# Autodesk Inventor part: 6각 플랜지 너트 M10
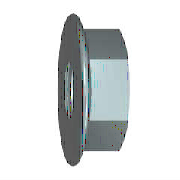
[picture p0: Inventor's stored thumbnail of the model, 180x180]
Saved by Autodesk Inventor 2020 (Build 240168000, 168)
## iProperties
Created: 2012-02
Part Number: 6각 플랜지 너트 M10
Material: 강철, 연강
Description: 플랜지붙이 6각 너트
Document SubType Name: Modeling
Standard: JIS B 1190
Designer: mdu-01
Standards Organization: JIS
Language: ko-KR
Size Designation: M 10
Categories: <MemberInstance><Categories><Category DisplayName="조임쇠" InternalName="e4da775c-781d-43d5-af7c-5136215cf5a6" Mnemonic="FSTN"><Category DisplayName="너트" InternalN
Density: 1 g/cm^3
Appearance: Steel
IsCustomPart: 1
Author: mdu-01
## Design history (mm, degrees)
sketch "스케치1"
  geometry: L1 (-2.276, 0)-(12.046, 0) reference; L2 (3.914, 7)-(2.239, 9.9); L3 (3.914, 7)-(10, 7); L4 (10, 7)-(10, 0); L5 (3.914, 7)-(3.914, 0); L6 (0, -2.152)-(0, 12.911) reference; A1 r 1.2 centre (1.2, 9.3) between (2.239, 9.9) and (0, 9.3); 1 further point
  constraints: 8 end point, 3 point on line, 2 perpendicular, 2 point on circle, 2 tangent, 1 centre point, 1 parallel
  dimensions: "d2" = 14 diameter of L3 L1 (= SW); "d4" = 21 dimension on A1 L1 (= LADI); "d5" = 1.2 radius of A1 (= PHH); "d15" = 10 distance between parallel lines of L4 L6 (= KOH); "d16" = 30 deg angle of L6 L2 (= KEWI)
revolve "링" sketch "스케치1" stored, may be unused: angle "d8" = 90 deg
sketch "스케치2"
  geometry: L1 (-7, -4.041)-(-7, 4.041); L2 (-7, 4.041)-(0, 8.083); L3 (0, 8.083)-(7, 4.041); L4 (7, 4.041)-(7, -4.041); L5 (7, -4.041)-(0, -8.083); L6 (0, -8.083)-(-7, -4.041); C1 r 4.9 at (0, 0); C2 r 9.3 at (0, 0) reference; 1 further point
  constraints: 12 end point, 1 centre point, 1 coincident, 1 vertical, 11 other
  dimensions: "d6" = 16.16581 distance of L5.end L2.end (= 1.1547 x SW)
extrude "본체" join sketch "스케치2" distance "d7" = 10 (= KOH); taper "d9" = 0 deg
sketch "스케치3"
  geometry: L1 (3.288, 8.083)-(10, 8.083) reference; L2 (10, 4.041)-(10, 8.083) reference; L3 (0, -9.3)-(0, 9.3) reference; L4 (-2, 0)-(12, 0) reference; L5 (9.375, 8.083)-(10, 7)
  constraints: 2 end point, 2 point on line
  dimensions: "d10" = 30 deg angle of L2 L5 (= ANG1); "d11" = 14 diameter of L5.end L4 (= SW0)
revolve "모따기1" sketch "스케치3" stored, may be unused: angle "d24" = 90 deg
sketch "스케치4"
  geometry: C1 r 9.3 at (0, 0) reference; 1 further point
  constraints: 1 coincident
hole "스레드" sketch "스케치4" at (0, 0) diameter "d25" = 8.376; stored, may be unused: countersink angle "d29" = 82 deg, drill point angle "d31" = 118 deg; dims "d26" = 6, "d27" = 4, "d28" = 2, "d30" = 8
workaxis "Work Axis1"
workplane "Work Plane1"
body "Solid1"
chamfer "모따기2" distance "d12" = 0.8119 (= -0.5 x GD1 + 0.5 x NND); stored, may be unused: angle "d13" = 30 deg, second distance "d46" = 0.8119 (= -0.5 x GD1 + 0.5 x NND)
chamfer "모따기3" distance "d51" = 0.8119 (= -0.5 x GD1 + 0.5 x NND); stored, may be unused: second distance "d52" = 2, angle "d53" = 45 deg
other parameters: "ANG1" = 30 deg [user parameter; used in 1 equation term], "KEWI" = 30 deg [user parameter; used in 1 equation term], "LADI" = 21 [user parameter; used in 2 equation terms], "SW" = 14 [user parameter; used in 3 equation terms], "PHH" = 1.2 [user parameter; used in 2 equation terms], "KOH" = 10 [user parameter; used in 2 equation terms], "SW0" = 14 [user parameter; used in 1 equation term], "GD1" = 8.3762 (computed from THREADDIA, PTC, TOA) [user parameter; used in 3 equation terms], "d1" = 21 (= LADI), "d3" = 1.2 (= PHH), "d45" = 0, "d47" = 0, "d49" = 0, "d54" = 0, "GUL" = 0.8119 (= 0.541266 x PTC) [user parameter], "TPU" = 6.66667 (computed from PTC) [user parameter], "RR" = 1.4 [user parameter], "TOA" = 30 deg [user parameter; used in 1 equation term], "PTC" = 1.5 [user parameter; used in 4 equation terms], "GAL" = 0.8119 (= 0.541266 x PTC) [user parameter], "E0" = 16.17 (= 1.155 x SW) [user parameter]
